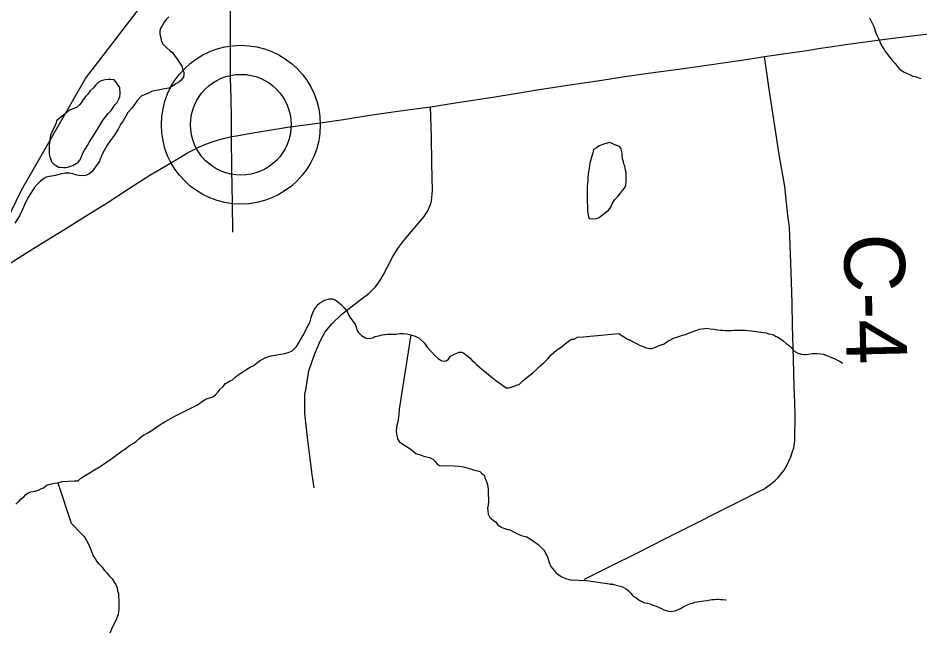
# Model space of a CAD drawing. Extents: x 103424 to 286016, y 38711 to 110967.
# Drawn here: x 129737 to 134224, y 78769 to 81798 of the extents above; entities that cross this region are included whole.
import ezdxf

# ---------------------------------------------------------------- set-up
doc = ezdxf.new("R2010")
doc.units = 0
for name, color, linetype in [('GM_X_County_Road_Text', 7, 'Continuous'), ('GM_X_Major_River', 7, 'Continuous'), ('GM_X_Minor_Lake', 7, 'Continuous'), ('GM_X_Minor_River', 7, 'Continuous'), ('GM_X_Rail_Line', 7, 'Continuous'), ('GM_X_Township_Road', 7, 'Continuous'), ('GM_X_Unincorporated', 7, 'Continuous'), ('GM_X_Unincorporated_Location', 7, 'Continuous'), ('GM_X_US_Route', 7, 'Continuous')]:
    doc.layers.add(name, color=color, linetype=linetype)

msp = doc.modelspace()

# ---------------------------------------------------------------- linework, layer by layer
at = {"layer": 'GM_X_Major_River'}
msp.add_lwpolyline([(130487.7, 81805), (130475.7, 81792.8), (130463.8, 81778.5), (130455.9, 81762.3), (130446, 81746), (130442.1, 81733.9), (130442.3, 81719.7), (130450.8, 81681.4), (130459, 81667.4), (130475.4, 81651.4), (130493.7, 81635.4), (130505.9, 81627.5), (130512.1, 81617.4), (130518.3, 81607.4), (130526.5, 81597.4), (130538.8, 81579.3), (130545, 81569.3), (130551.2, 81559.2), (130557.5, 81539.1), (130561.6, 81529), (130561.7, 81518.9), (130559.9, 81504.8), (130547.9, 81488.5), (130535.9, 81478.3), (130523.9, 81472.1), (130513.9, 81463.9), (130487.8, 81449.5), (130457.6, 81445.2), (130435.4, 81438.9), (130413.2, 81436.7), (130401.2, 81432.5), (130389.1, 81426.3), (130367, 81416), (130348.9, 81409.8), (130331, 81389.4), (130319, 81373.1), (130303.1, 81350.7), (130283.2, 81328.3), (130273.3, 81310), (130259.4, 81287.7), (130247.5, 81269.4), (130235.7, 81245), (130215.8, 81214.5), (130196, 81188), (130180.1, 81165.7), (130166.2, 81139.3), (130156.3, 81121), (130148.4, 81104.8), (130140.6, 81082.5), (130104.8, 81033.6), (130088.8, 81021.3), (130072.7, 81015.1), (130052.6, 81012.9), (130030.3, 81016.7), (130010, 81022.6), (129993.8, 81026.5), (129981.7, 81026.3), (129971.6, 81026.2), (129953.5, 81024), (129939.4, 81019.9), (129923.3, 81015.7), (129913.2, 81013.5), (129893, 81009.3), (129876.9, 81007.1), (129864.9, 81000.9), (129846.9, 80984.6), (129832.9, 80970.3), (129816.9, 80954), (129801.1, 80927.6), (129785.2, 80903.2), (129771.4, 80872.7), (129757.6, 80842.3), (129743.8, 80813.9), (129722, 80777.3)], dxfattribs=at)
at = {"layer": 'GM_X_Minor_Lake'}
for points in [[(130150.4, 81275.6), (130160.4, 81292.7), (130174.4, 81309), (130186.3, 81323.3), (130200.3, 81337.6), (130210.2, 81353.8), (130218.1, 81366), (130230.1, 81378.3), (130238, 81394.5), (130243.9, 81408.7), (130245.8, 81420.8), (130243.4, 81453.2), (130231, 81471.2), (130222.8, 81481.2), (130214.7, 81491.2), (130198.5, 81493.1), (130186.4, 81493), (130170.2, 81490.8), (130150.1, 81486.5), (130136, 81478.3), (130124.1, 81466.1), (130110.1, 81449.8), (130096.1, 81435.5), (130084.2, 81419.2), (130074.2, 81409), (130060.3, 81392.7), (130050.4, 81376.5), (130042.4, 81366.3), (130028.4, 81354), (130018.4, 81349.9), (130006.3, 81345.7), (129992.8, 81339.8)], [(129992.8, 81339.8), (129928.2, 81286.4), (129926.3, 81276.3), (129922.4, 81266.1), (129898.7, 81215.4), (129894.9, 81193.1), (129893.1, 81177), (129891.2, 81164.8), (129891.4, 81152.7), (129891.5, 81140.6), (129891.7, 81126.4), (129893.9, 81112.3), (129900.1, 81094.2), (129904.3, 81084.2), (129916.6, 81070.1), (129926.7, 81064.2), (129938.9, 81056.2), (129949.1, 81056.3), (129963.2, 81054.4), (129975.3, 81054.6), (129985.4, 81056.7), (129997.5, 81060.8), (130009.5, 81065), (130025.6, 81075.3), (130035.6, 81081.4), (130045.6, 81093.6), (130051.5, 81105.8), (130055.4, 81116), (130059.3, 81126.1), (130067.2, 81140.3), (130075.2, 81150.5), (130083.1, 81164.7), (130091, 81178.9), (130100.9, 81195.2), (130114.8, 81215.5), (130126.7, 81237.9), (130150.4, 81275.6)], [(132715, 81164.1), (132680.7, 81179.3), (132668.6, 81175), (132650.6, 81170.7), (132628.5, 81162.2), (132614.6, 81151.9), (132600.6, 81143.5), (132596.9, 81127.3), (132589.1, 81107), (132585.4, 81088.7), (132581.6, 81076.5), (132579.9, 81062.3), (132578.1, 81050.2), (132574.3, 81036), (132572.5, 81019.8), (132570.8, 81003.6), (132571.1, 80989.5), (132569.3, 80975.3), (132567.5, 80963.1), (132567.8, 80947), (132568, 80936.9), (132568.2, 80926.8), (132568.3, 80916.7), (132568.6, 80904.6), (132568.8, 80892.5), (132569, 80882.4), (132569.3, 80862.2), (132569.5, 80852.1), (132569.7, 80842), (132572, 80827.9), (132574.3, 80811.7)], [(132715, 81164.1), (132680.7, 81179.3), (132668.6, 81175), (132650.6, 81170.7), (132628.5, 81162.2), (132614.6, 81151.9), (132600.6, 81143.5), (132596.9, 81127.3), (132589.1, 81107), (132585.4, 81088.7), (132581.6, 81076.5), (132579.9, 81062.3), (132578.1, 81050.2), (132574.3, 81036), (132572.5, 81019.8), (132570.8, 81003.6), (132571.1, 80989.5), (132569.3, 80975.3), (132567.5, 80963.1), (132567.8, 80947), (132568, 80936.9), (132568.2, 80926.8), (132568.3, 80916.7), (132568.6, 80904.6), (132568.8, 80892.5), (132569, 80882.4), (132569.3, 80862.2), (132569.5, 80852.1), (132569.7, 80842), (132572, 80827.9), (132574.3, 80811.7), (132578.5, 80801.7), (132596.7, 80800), (132614.8, 80800.4), (132628.8, 80806.7), (132644.8, 80819.1), (132674.6, 80841.8), (132686.4, 80858.2), (132692.2, 80874.5), (132706, 80894.9), (132721.8, 80911.4), (132733.6, 80927.7), (132743.5, 80940), (132753.3, 80952.3), (132761.2, 80966.6), (132762.8, 80988.9), (132762.5, 81003), (132762.3, 81017.1), (132762.1, 81029.3), (132759.8, 81041.3), (132755.4, 81061.5), (132751.2, 81071.5), (132749, 81083.6), (132744.7, 81097.6), (132742.4, 81113.7), (132742.2, 81123.9), (132740, 81133.9), (132737.7, 81148), (132731.5, 81158), (132717.3, 81163.8), (132715, 81164.1)], [(132574.3, 80811.7), (132578.5, 80801.7), (132596.7, 80800), (132614.8, 80800.4), (132628.8, 80806.7), (132644.8, 80819.1), (132674.6, 80841.8), (132686.4, 80858.2), (132692.2, 80874.5), (132706, 80894.9), (132721.8, 80911.4), (132733.6, 80927.7), (132743.5, 80940), (132753.3, 80952.3), (132761.2, 80966.6), (132762.8, 80988.9), (132762.5, 81003), (132762.3, 81017.1), (132762.1, 81029.3), (132759.8, 81041.3), (132755.4, 81061.5), (132751.2, 81071.5), (132749, 81083.6), (132744.7, 81097.6), (132742.4, 81113.7), (132742.2, 81123.9), (132740, 81133.9), (132737.7, 81148), (132731.5, 81158), (132717.3, 81163.8), (132715, 81164.1)]]:
    msp.add_lwpolyline(points, dxfattribs=at)
at = {"layer": 'GM_X_Minor_River'}
for points in [[(133973.1, 81798.5), (133979.4, 81786.4), (133983.6, 81776.4), (133989.8, 81766.4), (133994, 81756.4), (133998.3, 81746.4), (134002.6, 81728.3), (134011, 81710.3), (134017.3, 81696.2), (134023.6, 81682.2), (134027.8, 81672.2), (134036.2, 81656.2), (134046.5, 81642.2), (134052.8, 81630.2), (134061.1, 81620.2), (134069.4, 81608.3), (134083.8, 81590.4), (134100.3, 81572.5), (134110.6, 81558.5), (134118.9, 81548.6), (134131.1, 81538.7), (134141.4, 81530.8), (134153.6, 81524.9), (134175.9, 81515.2), (134188.2, 81509.4), (134200.3, 81507.6), (134228.7, 81498)], [(130224.2, 79622.8), (130248.2, 79641.2), (130270.3, 79655.6), (130292.3, 79672), (130312.3, 79684.3), (130324.4, 79692.5), (130338.4, 79704.8), (130358.4, 79721.1), (130382.4, 79735.5), (130408.5, 79749.9), (130434.6, 79770.4), (130472.7, 79793), (130516.8, 79817.6), (130573, 79846.5), (130627.3, 79873.3), (130669.3, 79902), (130705.5, 79914.5), (130719.6, 79924.7), (130733.5, 79939), (130741.5, 79951.2), (130755.5, 79963.4), (130769.4, 79979.7), (130789.5, 79992.1), (130803.5, 79998.3), (130815.5, 80010.5), (130831.5, 80022.8), (130855.6, 80039.2), (130875.6, 80051.5), (130891.7, 80061.8), (130909.7, 80070), (130923.8, 80082.3), (130941.8, 80094.6), (130959.8, 80104.8), (130977.9, 80113.1), (130996.1, 80117.3), (131016.2, 80121.6), (131042.4, 80125.9), (131064.6, 80130.1), (131086.7, 80136.4), (131100.8, 80142.6), (131110.8, 80152.8), (131122.7, 80165.1), (131130.7, 80177.3), (131142.6, 80197.6), (131154.5, 80217.9), (131180.1, 80268.6), (131188, 80282.9), (131193.9, 80303.1), (131197.8, 80315.3), (131203.6, 80331.5), (131211.5, 80349.8), (131219.4, 80359.9), (131225.4, 80370.1), (131237.4, 80380.3), (131263.5, 80394.7), (131285.6, 80401), (131301.8, 80401.1), (131314, 80397.2), (131328.2, 80387.3), (131346.6, 80371.3), (131358.9, 80357.3), (131369.1, 80345.3), (131377.3, 80331.2), (131383.5, 80319.2), (131391.8, 80305.1), (131400, 80295.1), (131406.1, 80285), (131414.3, 80275), (131418.5, 80260.9), (131424.8, 80244.8), (131431, 80234.8), (131445.3, 80218.8), (131465.6, 80206.8), (131477.8, 80204.9), (131489.9, 80205.1), (131502, 80207.2), (131512, 80213.4), (131532.1, 80217.6), (131548.3, 80221.8), (131574.5, 80226.1), (131596.7, 80226.3), (131616.9, 80226.5), (131637, 80228.7), (131655.2, 80228.9), (131671.4, 80227.1), (131691.6, 80223.2), (131711.9, 80215.3), (131732.2, 80205.4), (131758.8, 80181.5), (131773.1, 80161.4), (131812, 80117.4), (131826.3, 80105.4), (131842.6, 80095.5), (131856.8, 80091.6), (131866.8, 80093.7), (131878.9, 80101.9), (131888.8, 80116.1), (131910.9, 80128.4), (131931, 80136.7), (131943.1, 80136.9), (131953.2, 80132.9)], [(131691.6, 80223.2), (131633.3, 79853), (131631.6, 79824.7), (131626, 79790.3), (131620.2, 79764), (131618.4, 79741.7), (131620.7, 79721.6), (131624.9, 79705.4), (131633.2, 79691.4), (131651.5, 79679.4), (131669.8, 79667.5), (131692.2, 79651.6), (131716.7, 79631.6), (131743, 79623.8), (131761.3, 79617.9), (131783.6, 79612.1), (131801.8, 79602.2), (131812.1, 79592.2), (131820.3, 79582.1), (131832.5, 79572.2), (131852.7, 79570.3), (131874.9, 79572.6), (131907.2, 79570.9), (131931.5, 79569.1), (131953.7, 79565.3), (131992.3, 79553.6), (132008.5, 79549.7), (132024.7, 79545.8), (132034.8, 79541.9), (132045, 79531.9), (132055.2, 79523.9), (132061.5, 79507.8), (132069.8, 79487.7), (132074, 79469.5), (132076.3, 79451.4), (132076.5, 79427.1), (132076.7, 79409), (132076.9, 79392.8), (132075.1, 79374.6), (132073.3, 79360.4), (132073.4, 79346.3), (132075.6, 79330.2), (132083.9, 79314.1), (132100.2, 79300.1), (132112.4, 79292.1), (132124.7, 79278.1), (132141, 79266.2), (132157.3, 79258.3), (132171.4, 79254.4), (132183.6, 79252.5), (132205.9, 79240.6), (132222.2, 79232.6), (132240.5, 79224.7), (132268.8, 79216.9), (132289.2, 79205), (132305.5, 79193.1), (132323.8, 79179.1), (132340.1, 79165.1), (132352.4, 79151.1), (132362.7, 79135.1), (132373, 79112.9), (132379.3, 79090.8), (132387.7, 79070.7), (132395.9, 79060.6), (132404.1, 79050.6), (132412.2, 79040.6), (132422.4, 79032.6), (132438.7, 79020.7), (132461.1, 79010.8), (132485.4, 79003), (132566, 79000.7)], [(132547.8, 80212.2), (132726, 80228.6), (132738.2, 80220.8), (132754.5, 80211), (132768.8, 80201.1), (132783.1, 80195.3), (132793.3, 80189.4), (132803.5, 80183.6), (132813.6, 80179.7), (132831.9, 80169.9), (132842.1, 80166.1), (132852.3, 80162.2), (132862.4, 80158.4), (132880.7, 80154.7), (132890.7, 80154.8), (132910.8, 80163.3), (132926.8, 80169.6), (132940.8, 80173.9), (132950.9, 80178.1), (132968.8, 80190.6), (132982.8, 80196.9), (132996.8, 80205.2), (133014.8, 80211.6), (133028.9, 80215.9), (133042.9, 80220.2), (133053, 80222.4), (133065, 80226.6), (133085, 80235.1), (133109.1, 80243.6), (133127.1, 80250), (133141.2, 80252.3), (133153.3, 80254.5), (133167.4, 80254.8), (133179.6, 80252.9), (133199.8, 80251.3), (133216, 80247.5), (133232.1, 80245.8), (133242.2, 80246), (133254.4, 80244.2), (133264.5, 80244.4), (133276.6, 80244.6), (133286.6, 80244.8), (133298.7, 80245), (133308.8, 80245.2), (133337.1, 80245.7), (133355.2, 80246), (133365.4, 80244.2), (133385.6, 80242.5), (133395.7, 80240.7), (133409.8, 80238.9), (133420, 80237.1), (133432.1, 80235.3), (133444.2, 80233.5), (133458.4, 80231.7), (133470.6, 80227.9), (133482.7, 80226.1), (133494.9, 80222.3), (133505.1, 80216.4), (133517.3, 80210.5), (133529.5, 80202.7), (133543.8, 80192.8), (133558.2, 80178.9), (133572.5, 80169.1), (133582.8, 80159.2), (133595.1, 80145.3), (133605.4, 80137.4), (133615.6, 80131.5), (133633.8, 80125.8), (133646, 80124), (133656.1, 80124.1), (133670.1, 80126.4), (133688.3, 80128.8), (133698.3, 80128.9), (133712.5, 80129.2), (133730.7, 80127.5), (133742.8, 80125.7), (133755, 80121.9), (133769.2, 80116.1), (133783.4, 80110.3), (133797.7, 80104.5), (133809.9, 80098.6), (133824.1, 80090.8), (133836.4, 80082.9), (133840.4, 80083)], [(131953.2, 80132.9), (131965.5, 80122.9), (131975.7, 80115), (131985.8, 80107), (131996.1, 80095), (132008.3, 80085), (132018.5, 80075), (132030.8, 80063), (132043, 80053), (132053.2, 80045), (132065.5, 80035), (132079.7, 80023.1), (132098.1, 80009.1), (132114.4, 79995.1), (132130.7, 79983.2), (132140.9, 79977.2), (132153.1, 79967.2), (132165.3, 79959.3), (132177.4, 79959.4), (132189.5, 79961.5), (132205.6, 79967.8), (132219.7, 79974), (132229.7, 79976.1), (132247.7, 79994.4), (132267.7, 80010.8), (132297.7, 80033.3), (132315.7, 80049.7), (132333.7, 80068), (132353.7, 80084.4), (132371.7, 80100.7), (132389.6, 80123.1), (132415.6, 80145.6), (132433.6, 80157.9), (132473.7, 80188.6), (132485.7, 80196.8), (132491.7, 80200.9), (132501.8, 80201), (132519.9, 80211.3), (132547.8, 80212.2)], [(129726.1, 79379.5), (129742.1, 79395.8), (129752, 79406), (129766.1, 79416.3), (129774, 79426.5), (129788.1, 79436.7), (129800.1, 79440.8), (129820.3, 79445.1), (129838.4, 79449.3), (129854.5, 79457.5), (129864.5, 79461.7), (129882.5, 79476), (129918.8, 79484.5), (129934.9, 79486.6), (129957.1, 79492.9), (129987.3, 79495.2), (130015.6, 79495.5), (130035.8, 79495.7), (130049.8, 79510), (130118, 79551.1), (130146.1, 79567.5), (130172.1, 79585.9), (130198.1, 79604.4), (130224.2, 79622.8)], [(129934.9, 79486.6), (130001.9, 79285.3), (130053, 79233.3), (130065.3, 79219.3), (130077.6, 79199.2), (130090, 79177.1), (130100.4, 79148.9), (130110.8, 79122.8), (130123.1, 79106.7), (130129.3, 79094.7), (130137.5, 79084.6), (130155.9, 79066.6), (130166.2, 79052.6), (130178.4, 79038.6), (130192.8, 79022.6), (130205, 79008.6), (130215.3, 78992.5), (130223.5, 78980.5), (130229.8, 78962.3), (130232, 78948.2), (130236.2, 78936.1), (130236.3, 78922), (130238.6, 78901.8), (130238.8, 78881.6), (130239.1, 78857.4), (130235.4, 78831.1), (130223.6, 78800.7), (130207.8, 78770.2), (130194, 78737.8)], [(132566, 79000.7), (132689.8, 78981.6), (132683.8, 78981.5), (132695.9, 78981.7), (132718.2, 78976), (132732.3, 78972.2), (132744.5, 78968.4), (132762.9, 78958.6), (132773.1, 78948.7), (132785.4, 78936.8), (132797.8, 78922.9), (132810, 78915.1), (132826.4, 78903.2), (132836.6, 78897.3), (132850.8, 78891.5), (132867, 78887.8), (132881.2, 78884), (132891.4, 78880.1), (132901.6, 78876.3), (132911.7, 78872.4), (132925.9, 78866.6), (132938.2, 78860.8), (132950.4, 78855), (132960.5, 78851.1), (132972.7, 78847.3), (132986.9, 78845.5), (133004.9, 78849.9), (133017, 78854.1), (133033, 78860.5), (133048.9, 78870.9), (133067, 78879.3), (133083, 78885.6), (133093, 78887.8), (133103.1, 78892), (133149.3, 78898.9), (133165.5, 78901.2), (133179.5, 78903.5), (133189.6, 78905.7), (133199.7, 78905.9), (133211.7, 78908.1), (133221.8, 78908.3), (133231.9, 78906.5), (133242, 78906.6), (133256.2, 78904.9), (133260.2, 78905)]]:
    msp.add_lwpolyline(points, dxfattribs=at)
at = {"layer": 'GM_X_Rail_Line'}
msp.add_lwpolyline([(128241.2, 78169.9), (128368.1, 78832.6), (128541.9, 79227.4), (128629.7, 79329.6), (129227.8, 79828.9), (129359.3, 80054.5), (129514.4, 80449.3), (129754, 80942.7), (130073.4, 81497.3), (130392.9, 81915.6), (130942.6, 82503), (131154, 82822.6), (131191.6, 83057.6), (131257.4, 83377.2), (131356, 83574.6), (131525.1, 83795.5), (131789.7, 83960.5), (132065.7, 84110.9), (132341.7, 84198.6), (132735.6, 84277.4), (133125.5, 84406.9), (133562.5, 84584.8), (133875.3, 84761), (134206.1, 85023.5)], dxfattribs=at)
at = {"layer": 'GM_X_Township_Road'}
for points in [[(130799, 81208.6), (130798.6, 81299.4), (130796.6, 81400.1), (130794.6, 81500.8), (130794.1, 81992.4)], [(133600.8, 79885), (133598.6, 79964.4), (133594.8, 80102.1), (133590.3, 80267.1), (133587.3, 80377.6), (133584.2, 80488.1), (133579.3, 80623.3), (133574.3, 80758.4), (133567.1, 80816.3), (133560.1, 80878.6), (133550.8, 80960), (133522.8, 81119.2), (133498.4, 81282.4), (133474.3, 81444.3), (133450.2, 81606.1)], [(131210.7, 79461.5), (131200.7, 79527), (131188.8, 79619.4), (131177, 79711.7), (131164.2, 79831), (131163.4, 79894.7), (131164.2, 79926.8), (131168.2, 79949.3), (131184.3, 80043), (131212.5, 80124), (131242.5, 80194.1), (131265.3, 80237.8), (131299.9, 80278.7), (131346.3, 80324.2), (131392.8, 80359.4), (131443.7, 80399.8), (131482.9, 80427.4), (131499.5, 80443.8), (131514.8, 80461.3), (131528.9, 80479.9), (131541.8, 80499.2), (131553.4, 80519.4), (131600.7, 80608.3), (131613.1, 80630.2), (131626.7, 80651.3), (131641.1, 80671.7), (131656.7, 80691.3), (131756.7, 80810.5), (131766.5, 80824.5), (131775.1, 80839.4), (131782.6, 80855.1), (131788.4, 80871.2), (131793.2, 80887.9), (131796.2, 80904.8), (131798.3, 80939.3), (131796.2, 81074.1), (131794, 81208.9), (131788.6, 81357.2)], [(130805.2, 80732.6), (130803.4, 80879.1), (130801.2, 81043.8), (130799, 81208.6)], [(132555, 79006.8), (132674.9, 79066), (132822.2, 79140.4), (132954.8, 79207.4), (133087.5, 79274.4), (133234.8, 79348.8), (133327.1, 79395.4), (133419.3, 79442.1), (133446.9, 79455.2), (133467.7, 79469.2), (133485.7, 79483.7), (133502.9, 79497.2), (133518.7, 79513), (133534.1, 79530.7), (133547.7, 79549.2), (133560.8, 79572.3), (133571.6, 79594.4), (133581.1, 79614.8), (133588.8, 79637.4), (133595.6, 79660), (133600.5, 79684.4), (133601.9, 79696.6), (133602.4, 79826.8), (133600.8, 79885)]]:
    msp.add_lwpolyline(points, dxfattribs=at)
at = {"layer": 'GM_X_Unincorporated'}
for radius in [395.3, 250.6]:
    msp.add_circle((130845.6, 81267.5), radius, dxfattribs=at)
at = {"layer": 'GM_X_Unincorporated_Location'}
msp.add_line((130845.6, 81267.5), (130845.6, 81267.5), dxfattribs=at)
at = {"layer": 'GM_X_US_Route'}
for points in [[(133729.7, 81647.8), (133777.7, 81655), (133865.5, 81667.5), (133953.3, 81680.1), (134050.2, 81693.7), (134169.3, 81708.2), (134268.3, 81719.9), (134336.2, 81723.4), (134494.4, 81733.8), (134652.5, 81744.1), (134745.1, 81748.3), (134760.5, 81749)], [(133729.7, 81647.8), (133777.7, 81655), (133865.5, 81667.5), (133953.3, 81680.1), (134050.2, 81693.7), (134169.3, 81708.2), (134268.3, 81719.9), (134336.2, 81723.4), (134494.4, 81733.8), (134652.5, 81744.1), (134745.1, 81748.3), (134760.5, 81749)], [(129684.3, 80571.2), (129824.5, 80658.3), (129964.8, 80745.3), (130072.9, 80812.3), (130180.9, 80879.4), (130286.7, 80948), (130392.4, 81016.6), (130471.7, 81063.4), (130551, 81110.3), (130580, 81127.4), (130609.5, 81143.2), (130639.7, 81157.6), (130670.6, 81170.6), (130702.1, 81182.3), (130734.1, 81192.5), (130766.6, 81201.3), (130799, 81208.6), (130823.2, 81213), (130877, 81222.3), (130976.9, 81238.5), (131076.9, 81254.7), (131216.4, 81274.4), (131356, 81294.1), (131487.7, 81315.8), (131638.1, 81336.5), (131788.6, 81357.2), (131944.1, 81380.9), (132099.7, 81404.5), (132209.5, 81422.6), (132319.3, 81440.7), (132482.5, 81465.5), (132619.3, 81486.2), (132756, 81507), (132883.7, 81524.9), (133011.4, 81542.7), (133174.8, 81566), (133267.2, 81579.2), (133359.6, 81592.4), (133450.2, 81606.1), (133542.9, 81619.9), (133660.3, 81637.4), (133729.7, 81647.8)], [(129684.3, 80571.2), (129824.5, 80658.3), (129964.8, 80745.3), (130072.9, 80812.3), (130180.9, 80879.4), (130286.7, 80948), (130392.4, 81016.6), (130471.7, 81063.4), (130551, 81110.3), (130580, 81127.4), (130609.5, 81143.2), (130639.7, 81157.6), (130670.6, 81170.6), (130702.1, 81182.3), (130734.1, 81192.5), (130766.6, 81201.3), (130799, 81208.6), (130823.2, 81213), (130877, 81222.3), (130976.9, 81238.5), (131076.9, 81254.7), (131216.4, 81274.4), (131356, 81294.1), (131487.7, 81315.8), (131638.1, 81336.5), (131788.6, 81357.2), (131944.1, 81380.9), (132099.7, 81404.5), (132209.5, 81422.6), (132319.3, 81440.7), (132482.5, 81465.5), (132619.3, 81486.2), (132756, 81507), (132883.7, 81524.9), (133011.4, 81542.7), (133174.8, 81566), (133267.2, 81579.2), (133359.6, 81592.4), (133450.2, 81606.1), (133542.9, 81619.9), (133660.3, 81637.4), (133729.7, 81647.8)]]:
    msp.add_lwpolyline(points, dxfattribs=at)

# ---------------------------------------------------------------- texts
at = {"layer": 'GM_X_County_Road_Text'}
msp.add_text('C-4', height=301.87, rotation=271.3741, dxfattribs=at).set_placement((133844.1, 80722.6))

doc.saveas('drawing.dxf')
